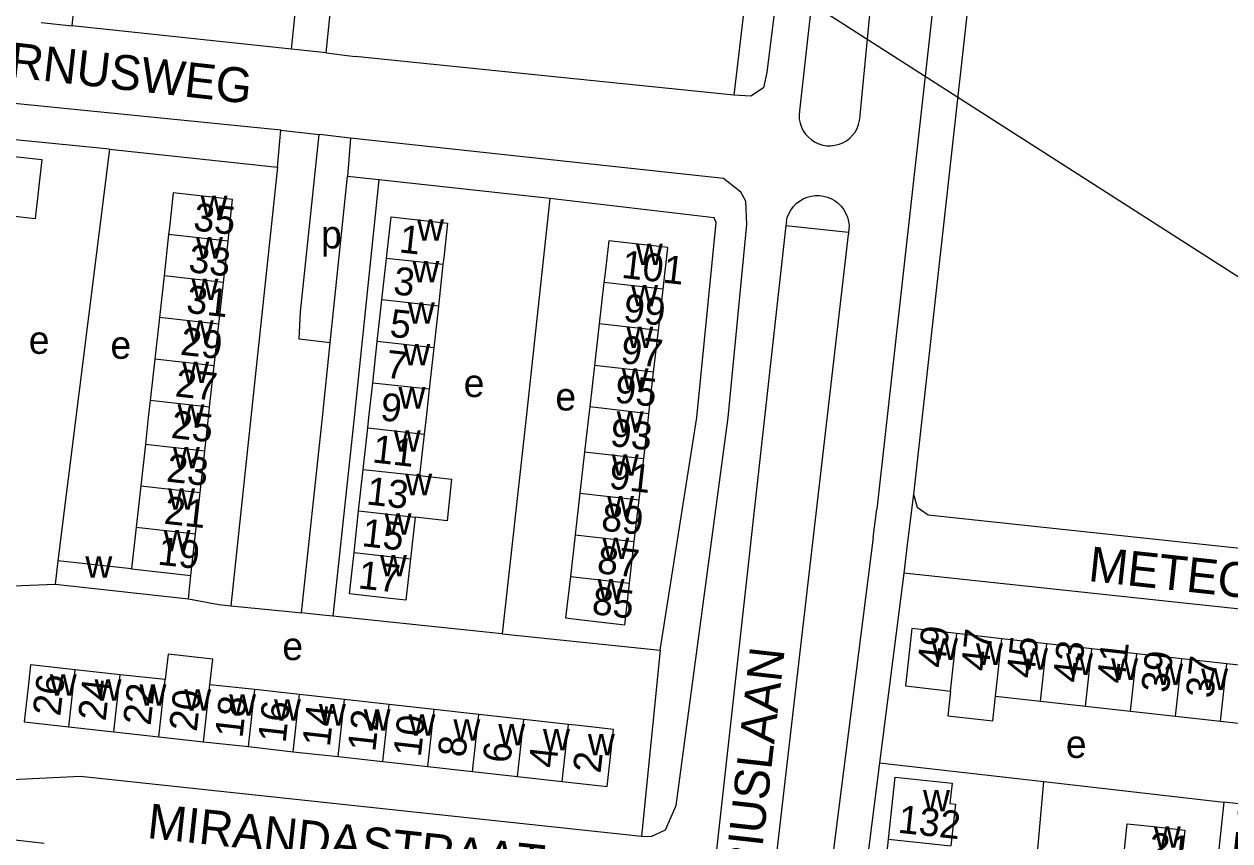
# Model space of a CAD drawing. Extents: x 161936 to 163647, y 386450 to 388633.
# Drawn here: x 162206.9 to 162379.9, y 387039.2 to 387156.5 of the extents above; entities that cross this region are included whole.
import ezdxf

# ---------------------------------------------------------------- set-up
doc = ezdxf.new("R2010")
doc.units = 0
for name, color, linetype in [('BLT_Basislijn', 7, 'Continuous'), ('BLT_Bebouwing', 7, 'Continuous'), ('BLT_Centroide', 7, 'Continuous'), ('BLT_Hoogspanningsmast_en_leidingen', 7, 'Continuous'), ('BLT_Huisnummer', 7, 'Continuous'), ('BLT_Huisnummer_ tussenligend', 7, 'Continuous'), ('BLT_Onderverdeling_panden', 7, 'Continuous'), ('BLT_Straatnaam', 7, 'Continuous'), ('BLT_Vlakafsluiter', 7, 'Continuous')]:
    doc.layers.add(name, color=color, linetype=linetype)

msp = doc.modelspace()

# ---------------------------------------------------------------- linework, layer by layer
at = {"layer": 'BLT_Basislijn'}
for p, q in [((162320.62, 387166.04), (162318.13, 387144)), ((162326.84, 387143.38), (162329.02, 387165.57)), ((162250.19, 387152.32), (162251.38, 387163.86)), ((162209.3, 387156.71), (162213.75, 387156.22)), ((162245.22, 387152.85), (162213.75, 387156.22)), ((162250.19, 387152.32), (162245.22, 387152.85)), ((162250.19, 387152.32), (162254.36, 387151.84)), ((162308.74, 387146.28), (162254.36, 387151.84)), ((162243.7, 387141.24), (162189.25, 387146.66)), ((162243.22, 387135.94), (162243.7, 387141.24)), ((162243.7, 387141.24), (162249.2, 387140.64)), ((162253.72, 387140.11), (162249.2, 387140.64)), ((162253.72, 387140.11), (162253.27, 387134.58)), ((162219.1, 387138.52), (162243.22, 387135.94)), ((162250.77, 387110.69), (162253.27, 387134.58)), ((162257.75, 387134.13), (162253.27, 387134.58)), ((162282.31, 387131.42), (162257.75, 387134.13)), ((162316.2, 387127.55), (162305.84, 387034.41)), ((162316.26, 387128.11), (162316.2, 387127.55)), ((162316.2, 387127.55), (162325.19, 387126.59)), ((162325.13, 387126.24), (162314.24, 387032.38)), ((162334.51, 387088.97), (162333.66, 387082.13)), ((162328.71, 387082.75), (162322.19, 387031.46)), ((162333.1, 387077.67), (162329.64, 387050.4)), ((162205.3, 387075.85), (162211.3, 387076.07)), ((162275.49, 387068.96), (162298.17, 387066.61)), ((162298.17, 387066.61), (162295.47, 387039.88)), ((162329.64, 387050.4), (162327.15, 387030.88)), ((162329.64, 387050.4), (162353.24, 387047.75)), ((162351.61, 387030.05), (162353.24, 387047.75)), ((162353.24, 387047.75), (162379.07, 387044.79)), ((162379.07, 387044.79), (162371.07, 386970.35)), ((162387.06, 387043.88), (162379.07, 387044.79)), ((162202.74, 387039.68), (162209.75, 387038.9))]:
    msp.add_line(p, q, dxfattribs=at)
for points in [[(162324.81, 387250), (162323.27, 387232.8), (162317.38, 387181.01), (162313.45, 387149.51), (162312.99, 387147.3), (162311.18, 387146.14), (162308.74, 387146.28)], [(162213.75, 387156.22), (162219.05, 387206.31), (162222.22, 387206.2), (162313.91, 387196.29), (162314.14, 387195.88), (162313.23, 387184.36), (162308.74, 387146.28)], [(162340.92, 387191.74), (162337.98, 387165.34), (162329.24, 387086.82)], [(162342.41, 387159.96), (162334.51, 387088.97)], [(162318.13, 387144), (162318.09, 387143.41), (162318.12, 387142.82), (162318.24, 387142.24), (162318.43, 387141.68), (162318.69, 387141.15), (162319.03, 387140.66), (162319.42, 387140.22), (162319.88, 387139.84), (162320.38, 387139.53), (162320.91, 387139.28), (162321.48, 387139.11), (162322.06, 387139.01), (162322.65, 387139), (162323.24, 387139.07), (162323.82, 387139.21), (162324.37, 387139.43), (162324.88, 387139.72), (162325.35, 387140.08), (162325.77, 387140.5), (162326.12, 387140.97), (162326.42, 387141.49), (162326.63, 387142.04), (162326.78, 387142.61), (162326.84, 387143.2), (162326.84, 387143.38)], [(162219.1, 387138.52), (162197.76, 387140.64), (162193.69, 387141.04)], [(162250.77, 387110.69), (162246.34, 387111.24), (162246.5, 387115.17), (162249.2, 387140.64)], [(162295.47, 387039.88), (162296.88, 387039.83), (162298.89, 387040.82), (162300.43, 387044.31), (162307.93, 387100), (162310.6, 387127.72), (162310.44, 387131.06), (162309.71, 387132.32), (162307.26, 387134.28), (162253.72, 387140.11)], [(162219.1, 387138.52), (162211.67, 387079.44)], [(162243.22, 387135.94), (162239.37, 387100), (162236.51, 387072.98)], [(162257.75, 387134.13), (162254.21, 387100), (162251.14, 387071.47)], [(162282.31, 387131.42), (162278.93, 387100), (162275.49, 387068.96)], [(162298.17, 387066.61), (162303.43, 387100), (162306.18, 387128), (162305.89, 387128.67), (162282.31, 387131.42)], [(162316.26, 387128.11), (162316.4, 387128.69), (162316.62, 387129.25), (162316.91, 387129.78), (162317.27, 387130.26), (162317.69, 387130.7), (162318.16, 387131.07), (162318.68, 387131.38), (162319.23, 387131.61), (162319.81, 387131.78), (162320.41, 387131.86), (162321.01, 387131.86), (162321.61, 387131.79), (162322.19, 387131.63), (162322.74, 387131.4), (162323.27, 387131.1), (162323.74, 387130.73), (162324.16, 387130.3), (162324.53, 387129.82), (162324.82, 387129.29), (162325.05, 387128.74), (162325.19, 387128.15), (162325.26, 387127.55), (162325.25, 387126.95), (162325.19, 387126.59)], [(162325.19, 387126.59), (162325.16, 387126.36), (162325.13, 387126.24)], [(162246.66, 387071.94), (162249.66, 387100), (162250.77, 387110.69)], [(162334.51, 387088.97), (162335.06, 387087.1), (162336.6, 387086)], [(162336.6, 387086), (162390.8, 387080.24), (162392.61, 387080.02)], [(162389.85, 387071.58), (162333.1, 387077.67)], [(162230.43, 387073.94), (162234.79, 387073.16), (162236.51, 387072.98)], [(162236.51, 387072.98), (162244.84, 387072.13), (162246.66, 387071.94)], [(162251.14, 387071.47), (162249.24, 387071.67), (162246.66, 387071.94)], [(162275.49, 387068.96), (162273.61, 387069.15), (162251.14, 387071.47)], [(162202.14, 387047.86), (162214.96, 387048.51), (162295.47, 387039.88)]]:
    msp.add_lwpolyline(points, dxfattribs=at)
at = {"layer": 'BLT_Bebouwing'}
for p, q in [((162245.22, 387152.85), (162246.42, 387164.49)), ((162227.59, 387126.27), (162226.93, 387120.31)), ((162235.46, 387119.36), (162236.12, 387125.32)), ((162258.21, 387116.87), (162258.87, 387122.83)), ((162266.97, 387121.94), (162266.31, 387115.97)), ((162226.93, 387120.31), (162226.27, 387114.34)), ((162234.8, 387113.4), (162235.46, 387119.36)), ((162290.08, 387119.39), (162289.4, 387113.43)), ((162297.89, 387112.46), (162298.57, 387118.42)), ((162257.55, 387110.9), (162258.21, 387116.87)), ((162266.31, 387115.97), (162265.65, 387110.01)), ((162226.27, 387114.34), (162225.61, 387108.38)), ((162234.14, 387107.43), (162234.8, 387113.4)), ((162289.4, 387113.43), (162288.72, 387107.47)), ((162297.21, 387106.5), (162297.89, 387112.46)), ((162256.89, 387104.94), (162257.55, 387110.9)), ((162265.65, 387110.01), (162264.99, 387104.05)), ((162225.61, 387108.38), (162224.95, 387102.42)), ((162233.48, 387101.47), (162234.14, 387107.43)), ((162288.72, 387107.47), (162288.04, 387101.51)), ((162296.53, 387100.54), (162297.21, 387106.5)), ((162255.53, 387092.55), (162256.19, 387098.52)), ((162264.28, 387097.61), (162263.62, 387091.65)), ((162224.25, 387096.16), (162223.59, 387090.2)), ((162232.12, 387089.24), (162232.79, 387095.2)), ((162287.3, 387095.07), (162286.62, 387089.11)), ((162254.87, 387086.59), (162255.53, 387092.55)), ((162295.12, 387088.15), (162295.8, 387094.11)), ((162223.59, 387090.2), (162222.93, 387084.23)), ((162231.46, 387083.28), (162232.12, 387089.24)), ((162286.62, 387089.11), (162285.94, 387083.14)), ((162294.43, 387082.19), (162295.12, 387088.15)), ((162254.21, 387080.63), (162254.87, 387086.59)), ((162262.97, 387085.68), (162262.31, 387079.72)), ((162285.94, 387083.14), (162285.26, 387077.18)), ((162293.75, 387076.23), (162294.43, 387082.19)), ((162347.18, 387068.24), (162340.72, 387068.97)), ((162353.64, 387067.52), (162347.18, 387068.24)), ((162360.11, 387066.8), (162353.64, 387067.52)), ((162366.57, 387066.08), (162360.11, 387066.8)), ((162373.03, 387065.35), (162366.57, 387066.08)), ((162379.49, 387064.63), (162373.03, 387065.35)), ((162220.64, 387063.07), (162214.2, 387063.79)), ((162227.08, 387062.36), (162220.64, 387063.07)), ((162239.95, 387060.93), (162233.51, 387061.64)), ((162246.39, 387060.22), (162239.95, 387060.93)), ((162252.82, 387059.5), (162246.39, 387060.22)), ((162346.26, 387060.01), (162352.72, 387059.28)), ((162259.26, 387058.79), (162252.82, 387059.5)), ((162265.7, 387058.07), (162259.26, 387058.79)), ((162272.13, 387057.36), (162265.7, 387058.07)), ((162352.72, 387059.28), (162359.18, 387058.56)), ((162359.18, 387058.56), (162365.65, 387057.84)), ((162365.65, 387057.84), (162372.11, 387057.11)), ((162278.57, 387056.64), (162272.13, 387057.36)), ((162285.01, 387055.93), (162278.57, 387056.64)), ((162372.11, 387057.11), (162378.57, 387056.39)), ((162213.29, 387055.6), (162219.73, 387054.88)), ((162219.73, 387054.88), (162226.17, 387054.17)), ((162226.17, 387054.17), (162232.6, 387053.45)), ((162232.6, 387053.45), (162239.04, 387052.74)), ((162239.04, 387052.74), (162245.48, 387052.02)), ((162245.48, 387052.02), (162251.91, 387051.31)), ((162251.91, 387051.31), (162258.35, 387050.6)), ((162258.35, 387050.6), (162264.79, 387049.88)), ((162264.79, 387049.88), (162271.23, 387049.17)), ((162271.23, 387049.17), (162277.66, 387048.45)), ((162277.66, 387048.45), (162284.1, 387047.74)), ((162330.28, 387033.46), (162330.92, 387039.46))]:
    msp.add_line(p, q, dxfattribs=at)
for points in [[(162197.22, 387135.69), (162200.66, 387135.3), (162200.95, 387137.96), (162209.38, 387137.04), (162208.44, 387128.51), (162205.02, 387128.89), (162205.01, 387128.78)], [(162236.12, 387125.32), (162236.78, 387131.29), (162228.25, 387132.23), (162227.7, 387127.26), (162227.59, 387126.27)], [(162258.87, 387122.83), (162259.53, 387128.8), (162267.63, 387127.9), (162267.08, 387122.93), (162266.97, 387121.94)], [(162298.57, 387118.42), (162299.25, 387124.39), (162290.76, 387125.35), (162290.19, 387120.39), (162290.08, 387119.39)], [(162256.19, 387098.52), (162256.35, 387100), (162256.89, 387104.94)], [(162264.99, 387104.05), (162264.55, 387100), (162264.28, 387097.61)], [(162224.95, 387102.42), (162224.68, 387100), (162224.25, 387096.16)], [(162232.79, 387095.2), (162233.32, 387100), (162233.48, 387101.47)], [(162288.04, 387101.51), (162287.86, 387100), (162287.3, 387095.07)], [(162295.8, 387094.11), (162296.47, 387100), (162296.53, 387100.54)], [(162263.62, 387091.65), (162268.22, 387091.12), (162267.56, 387085.15), (162262.97, 387085.68)], [(162222.93, 387084.23), (162222.27, 387078.27)], [(162230.8, 387077.32), (162231.46, 387083.28)], [(162262.31, 387079.72), (162261.65, 387073.77), (162258.52, 387074.11), (162253.55, 387074.66), (162254.21, 387080.63)], [(162211.67, 387079.44), (162211.3, 387076.07)], [(162222.27, 387078.27), (162211.67, 387079.44)], [(162230.43, 387073.94), (162230.8, 387077.32)], [(162285.26, 387077.18), (162284.58, 387071.22), (162288.11, 387070.82), (162293.07, 387070.25), (162293.75, 387076.23)], [(162211.3, 387076.07), (162230.43, 387073.94)], [(162340.72, 387068.97), (162334.26, 387069.69), (162333.34, 387061.45), (162338.3, 387060.9), (162339.8, 387060.73)], [(162233.51, 387061.64), (162233.92, 387065.31), (162227.51, 387066.03), (162227.08, 387062.36)], [(162214.2, 387063.79), (162207.77, 387064.5), (162207.41, 387061.28), (162206.86, 387056.31), (162213.29, 387055.6)], [(162378.57, 387056.39), (162385.03, 387055.67), (162385.39, 387058.94), (162385.95, 387063.91), (162379.49, 387064.63)], [(162339.8, 387060.73), (162339.42, 387057.18), (162345.88, 387056.46), (162346.26, 387060.01)], [(162284.1, 387047.74), (162290.53, 387047.02), (162291.44, 387055.21), (162286.47, 387055.76), (162285.01, 387055.93)], [(162330.92, 387039.46), (162331.87, 387048.35), (162340.05, 387047.48), (162339.75, 387044.58), (162340.55, 387044.5)], [(162340.55, 387044.5), (162339.87, 387038.5)], [(162364.55, 387035.68), (162365.2, 387041.68), (162368.51, 387041.31), (162373.48, 387040.76), (162372.81, 387034.79)]]:
    msp.add_lwpolyline(points, dxfattribs=at)
at = {"layer": 'BLT_Hoogspanningsmast_en_leidingen'}
msp.add_line((162209.53, 387230.13), (162450.47, 387075.79), dxfattribs=at)
at = {"layer": 'BLT_Onderverdeling_panden'}
for p, q in [((162236.12, 387125.32), (162227.59, 387126.27)), ((162266.97, 387121.94), (162258.87, 387122.83)), ((162235.46, 387119.36), (162226.93, 387120.31)), ((162298.57, 387118.42), (162290.08, 387119.39)), ((162266.31, 387115.97), (162258.21, 387116.87)), ((162234.8, 387113.4), (162226.27, 387114.34)), ((162297.89, 387112.46), (162289.4, 387113.43)), ((162265.65, 387110.01), (162257.55, 387110.9)), ((162234.14, 387107.43), (162225.61, 387108.38)), ((162297.21, 387106.5), (162288.72, 387107.47)), ((162264.99, 387104.05), (162256.89, 387104.94)), ((162233.48, 387101.47), (162224.95, 387102.42)), ((162296.53, 387100.54), (162288.04, 387101.51)), ((162256.19, 387098.52), (162264.28, 387097.61)), ((162224.25, 387096.16), (162232.79, 387095.2)), ((162287.3, 387095.07), (162295.8, 387094.11)), ((162255.53, 387092.55), (162263.62, 387091.65)), ((162223.59, 387090.2), (162232.12, 387089.24)), ((162286.62, 387089.11), (162295.12, 387088.15)), ((162254.87, 387086.59), (162262.97, 387085.68)), ((162222.93, 387084.23), (162231.46, 387083.28)), ((162285.94, 387083.14), (162294.43, 387082.19)), ((162254.21, 387080.63), (162262.31, 387079.72)), ((162222.27, 387078.27), (162230.8, 387077.32)), ((162285.26, 387077.18), (162293.75, 387076.23)), ((162339.8, 387060.73), (162340.72, 387068.97)), ((162346.26, 387060.01), (162347.18, 387068.24)), ((162352.72, 387059.28), (162353.64, 387067.52)), ((162359.18, 387058.56), (162360.11, 387066.8)), ((162365.65, 387057.84), (162366.57, 387066.08)), ((162372.11, 387057.11), (162373.03, 387065.35)), ((162213.29, 387055.6), (162214.2, 387063.79)), ((162219.73, 387054.88), (162220.64, 387063.07)), ((162378.57, 387056.39), (162379.49, 387064.63)), ((162226.17, 387054.17), (162227.08, 387062.36)), ((162232.6, 387053.45), (162233.51, 387061.64)), ((162239.04, 387052.74), (162239.95, 387060.93)), ((162245.48, 387052.02), (162246.39, 387060.22)), ((162251.91, 387051.31), (162252.82, 387059.5)), ((162258.35, 387050.6), (162259.26, 387058.79)), ((162264.79, 387049.88), (162265.7, 387058.07)), ((162271.23, 387049.17), (162272.13, 387057.36)), ((162277.66, 387048.45), (162278.57, 387056.64)), ((162284.1, 387047.74), (162285.01, 387055.93)), ((162330.92, 387039.46), (162339.87, 387038.5))]:
    msp.add_line(p, q, dxfattribs=at)
at = {"layer": 'BLT_Vlakafsluiter'}
for p, q in [((162328.71, 387082.75), (162329.24, 387086.82)), ((162333.66, 387082.13), (162333.1, 387077.67))]:
    msp.add_line(p, q, dxfattribs=at)

# ---------------------------------------------------------------- texts
at = {"layer": 'BLT_Centroide'}
for s, p in [('w', (162232.18, 387128.78)), ('p', (162249.47, 387124.27)), ('w', (162263.25, 387125.38)), ('w', (162231.52, 387122.81)), ('w', (162294.66, 387121.88)), ('w', (162262.59, 387119.41)), ('w', (162230.87, 387116.84)), ('w', (162293.98, 387115.94)), ('w', (162261.93, 387113.44)), ('w', (162230.2, 387110.88)), ('e', (162207.52, 387109.13)), ('e', (162219.24, 387108.42)), ('w', (162293.3, 387109.97)), ('w', (162261.27, 387107.47)), ('w', (162229.54, 387104.94)), ('w', (162292.62, 387104)), ('e', (162269.95, 387102.93)), ('w', (162260.59, 387101.28)), ('e', (162283.11, 387101)), ('w', (162228.87, 387098.81)), ('w', (162291.91, 387097.81)), ('w', (162259.91, 387095.09)), ('w', (162228.2, 387092.69)), ('w', (162291.21, 387091.62)), ('w', (162261.55, 387088.84)), ('w', (162227.52, 387086.75)), ('w', (162290.53, 387085.66)), ('w', (162258.59, 387083.16)), ('w', (162226.87, 387080.78)), ('w', (162289.85, 387079.69)), ('w', (162215.64, 387076.98)), ('w', (162257.93, 387077.19)), ('w', (162289.16, 387073.72)), ('e', (162243.92, 387065.17)), ('w', (162337.03, 387065.2)), ('w', (162343.48, 387064.48)), ('w', (162349.95, 387063.77)), ('w', (162356.41, 387063.05)), ('w', (162362.88, 387062.33)), ('w', (162210.53, 387060.05)), ('w', (162369.34, 387061.59)), ('w', (162375.8, 387060.86)), ('w', (162216.97, 387059.33)), ('w', (162223.41, 387058.62)), ('w', (162229.84, 387057.91)), ('w', (162236.28, 387057.19)), ('w', (162242.72, 387056.48)), ('w', (162249.16, 387055.77)), ('w', (162255.59, 387055.05)), ('w', (162262.03, 387054.33)), ('w', (162268.47, 387053.61)), ('w', (162274.91, 387052.91)), ('w', (162281.33, 387052.19)), ('w', (162287.77, 387051.48)), ('e', (162356.38, 387051.12)), ('w', (162335.88, 387043.44)), ('w', (162369.01, 387038.22))]:
    msp.add_text(s, height=4, dxfattribs=at).set_placement(p)
at = {"layer": 'BLT_Huisnummer'}
for s, rotation, p in [('35', 353.6694, (162231.03, 387126.86)), ('1', 353.694, (162260.56, 387123.71)), ('101', 353.4836, (162292.49, 387120.06)), ('31', 353.6687, (162230.02, 387115.04)), ('5', 353.694, (162259.21, 387111.61)), ('97', 353.477, (162292.37, 387107.83)), ('27', 353.6687, (162228.41, 387103.04)), ('9', 353.6163, (162257.86, 387099.61)), ('93', 353.6109, (162290.85, 387095.92)), ('23', 353.6104, (162227.16, 387090.82)), ('13', 353.6163, (162255.87, 387087.53)), ('89', 353.6117, (162289.57, 387083.79)), ('19', 353.6839, (162225.91, 387078.89)), ('17', 353.6965, (162254.67, 387075.48)), ('85', 353.4877, (162288.23, 387071.78)), ('49', 83.6125, (162339.02, 387063.94)), ('43', 83.6125, (162358.45, 387061.81)), ('39', 83.6125, (162371.13, 387060.36)), ('26', 83.666, (162212.04, 387057.03)), ('22', 83.6652, (162225, 387055.69)), ('18', 83.6637, (162238.19, 387053.89)), ('14', 83.6629, (162250.73, 387052.63)), ('10', 83.669, (162263.79, 387051.16)), ('6', 83.6675, (162276.63, 387050.26)), ('2', 83.6598, (162289.58, 387048.83)), ('132', 353.8927, (162332.17, 387040.4)), ('21', 353.8452, (162368.14, 387036.49))]:
    msp.add_text(s, height=4, rotation=rotation, dxfattribs=at).set_placement(p)
at = {"layer": 'BLT_Huisnummer_ tussenligend'}
for s, rotation, p in [('33', 353.6687, (162230.33, 387120.88)), ('3', 353.694, (162259.73, 387117.69)), ('99', 353.477, (162292.75, 387113.82)), ('29', 353.6687, (162229.16, 387109.02)), ('7', 353.694, (162258.64, 387105.73)), ('95', 353.6109, (162291.51, 387102.18)), ('25', 353.6104, (162227.82, 387097.08)), ('11', 353.6163, (162256.72, 387093.56)), ('91', 353.6117, (162290.68, 387089.81)), ('21', 353.6839, (162226.82, 387084.76)), ('15', 353.6163, (162255.21, 387081.54)), ('87', 353.4877, (162288.97, 387077.67)), ('47', 83.6125, (162345.27, 387063.46)), ('45', 83.6125, (162351.8, 387062.45)), ('41', 83.6125, (162364.78, 387061.7)), ('37', 83.6142, (162377.53, 387059.59)), ('24', 83.6652, (162218.55, 387056.33)), ('20', 83.6637, (162231.62, 387054.81)), ('16', 83.6629, (162244.37, 387053.19)), ('12', 83.669, (162257.25, 387051.92)), ('8', 83.6675, (162270.18, 387051.11)), ('4', 83.6598, (162283.22, 387049.57))]:
    msp.add_text(s, height=4, rotation=rotation, dxfattribs=at).set_placement(p)
at = {"layer": 'BLT_Straatnaam'}
for s, height, rotation, p in [('SATURNUSWEG', 5, 353.6104, (162186.86, 387150.88)), ('METEOORSTRAAT', 5, 353.8343, (162359.49, 387076.53)), ('MERCURIUSLAAN', 4.9999, 83.5708, (162309.55, 387009.11)), ('MIRANDASTRAAT', 5, 353.9308, (162224.4, 387039.63)), ('KOMPASWEG', 5, 83.8221, (162381.59, 387001.24))]:
    msp.add_text(s, height=height, rotation=rotation, dxfattribs=at).set_placement(p)

doc.saveas('drawing.dxf')
